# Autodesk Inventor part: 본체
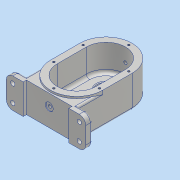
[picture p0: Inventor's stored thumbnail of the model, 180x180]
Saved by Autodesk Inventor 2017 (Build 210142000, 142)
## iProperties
Part Number: 본체
Material: 알루미늄 6061
Document SubType Name: Modeling
Designer: MRC
Density: 2.7 g/cm^3
Appearance: 알루미늄 - 평지
Mass: 755.763 g
Surface Area: 583.989 cm^2
Volume: 279.912 cm^3
Author: MRC
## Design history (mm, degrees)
sketch "스케치1"
  geometry: L1 (0, 0)-(0, 45); L2 (40, 0)-(40, 45); L3 (-40, 45)-(-40, 0); A1 r 40 centre (0, 0) between (-40, 0) and (40, 0); A2 r 40 centre (0, 45) between (40, 45) and (-40, 45); 1 further point
  constraints: 8 end point, 4 point on circle, 4 tangent, 2 centre point, 1 midpoint, 1 parallel, 1 vertical
  dimensions: "d0" = 80 distance between parallel lines of L3 L2; "d1" = 45 distance of L1.start L1.end
extrude "돌출1" new body sketch "스케치1" distance "d2" = 49; taper "d3" = 0 deg
feature "쉘1" dims "d4" = 10, "d113" = 8
sketch "스케치2"
  geometry: L1 (0, 45)-(0, 0); L2 (-26, 45)-(-26, 0); L3 (26, 0)-(26, 45); A1 r 40 centre (0, 0) between (-40, 0) and (40, 0) reference; A2 r 40 centre (0, 45) between (40, 45) and (-40, 45) reference; A3 r 26 centre (0, 45) between (26, 45) and (-26, 45); A4 r 26 centre (0, 0) between (-26, 0) and (26, 0); 1 further point
  constraints: 8 end point, 4 point on circle, 4 tangent, 2 centre point, 1 midpoint, 1 parallel, 1 vertical
  dimensions: "d5" = 52 distance between parallel lines of L3 L2
extrude "돌출2" join sketch "스케치2" distance "d6" = 11; taper "d7" = 0 deg
sketch "스케치3"
  geometry: L1 (-26, 75)-(26, 75); L2 (26, 75)-(26, 15); L3 (26, 15)-(-26, 15); L4 (-26, 15)-(-26, 75); A1 r 26 centre (0, 45) between (26, 45) and (-26, 45) reference; 2 further points
  constraints: 8 end point, 2 midpoint, 2 parallel, 1 horizontal, 1 horizontal alignment, 1 perpendicular, 1 vertical alignment
  dimensions: "d8" = 30 distance of A1.centre point (0, 15); "d9" = 52 distance of L2.end L3.end
extrude "돌출3" cut sketch "스케치3" distance "d10" = 3; taper "d11" = 0 deg
sketch "스케치4"
  geometry: A1 r 30 centre (0, -45) between (-30, -45) and (30, -45) reference; 1 further point
  constraints: 1 coincident
hole "구멍1" sketch "스케치4" at (0, -45) diameter "d12" = 20; stored, may be unused: countersink angle "d16" = 90 deg, drill point angle "d18" = 0 deg; dims "d13" = 6, "d14" = 28, "d15" = 8, "d17" = 12
sketch "스케치5"
  geometry: C1 r 14 at (0, 0); A1 r 30 centre (0, 0) between (30, 0) and (-30, 0) reference
  constraints: 1 centre point, 1 coincident
  dimensions: "d19" = 28 diameter of C1
extrude "돌출4" cut sketch "스케치5" distance "d20" = 8; taper "d21" = 0 deg
sketch "스케치6"
  geometry: A1 r 26 centre (0, 45) between (26, 45) and (-26, 45) reference; 2 further points
  constraints: 1 coincident
hole "구멍2" sketch "스케치6" at (0, 45) diameter "d22" = 22; stored, may be unused: countersink angle "d26" = 90 deg, drill point angle "d28" = 0 deg; dims "d23" = 6, "d24" = 28, "d25" = 4, "d27" = 12
sketch "스케치7"
  geometry: L1 (-61, -37)-(61, -37); L2 (61, -37)-(61, -47); L3 (61, -47)-(-61, -47); L4 (-61, -47)-(-61, -37); L5 (-40, 0)-(-40, -37); L6 (40, 0)-(40, -37); A1 r 26 centre (0, 45) between (26, 45) and (-26, 45) reference; A2 r 26 centre (0, 0) between (-26, 0) and (26, 0) reference; A3 r 40 centre (0, 0) between (-40, 0) and (40, 0) reference; 1 further point
  constraints: 12 end point, 2 parallel, 2 perpendicular, 2 point on line, 1 horizontal, 1 midpoint, 1 point on circle, 1 tangent, 1 vertical, 1 vertical alignment
  dimensions: "d29" = 10 distance of L3.end L1.start; "d30" = 47 distance from line of L3 A2.centre; "d31" = 122 distance of L2.end L3.end
extrude "돌출5" join sketch "스케치7" distance "d32" = 46; taper "d33" = 0 deg
sketch "스케치11"
  geometry: L1 (-61, -47)-(61, -47) reference; L2 (-35, -42)-(35, -42); L3 (35, -42)-(35, -47); L4 (35, -47)-(-35, -47); L5 (-35, -47)-(-35, -42); 3 further points
  constraints: 8 end point, 4 midpoint, 2 parallel, 1 horizontal, 1 perpendicular, 1 vertical alignment
  dimensions: "d39" = 5 distance of L2.end L3.end; "d40" = 70 distance of L3.end L4.end
extrude "돌출7" cut sketch "스케치11" stored distance "d41" = 38; taper "d42" = 0 deg
node "작업 평면1"
sketch "스케치12"
  geometry: C1 r 6 at (-61, 28); 1 further point
  constraints: 1 centre point
  dimensions: "d44" = 12 diameter of C1; "d45" = 21 distance of point (-61, 49) C1.centre
extrude "돌출8" join sketch "스케치12" stored distance "d46" = 12 (= d44); taper "d47" = 0 deg
sketch "스케치13"
  geometry: C1 r 6 at (0, 0) reference; 2 further points
  constraints: 1 coincident
hole "구멍3" sketch "스케치13" at (0, 0) diameter "d48" = 4.917; stored, may be unused: countersink angle "d52" = 90 deg, drill point angle "d54" = 0 deg; dims "d49" = 12, "d50" = 28, "d51" = 4, "d53" = 17.1
sketch "스케치14"
  geometry: A1 r 30 centre (0, 45) between (30, 45) and (-30, 45) reference; A2 r 30 centre (0, 0) between (-30, 0) and (30, 0) reference; 6 further points
  constraints: 4 horizontal alignment, 2 vertical alignment
  dimensions: "d55" = 35 distance of point (0, 80) A1.centre; "d56" = 35 distance of A2.centre point (0, -35); "d83" = 35 distance of point (-35, 45) A1.centre; "d84" = 35 distance of A2.centre point (-35, 0); "d85" = 35 distance of point (35, 0) A2.centre; "d86" = 35 distance of point (35, 45) A1.centre
hole "구멍4" sketch "스케치14" at (0, 80), (0, -35), (-35, 45), (-35, 0), (35, 0), (35, 45) diameter "d57" = 3.242; stored, may be unused: countersink angle "d61" = 90 deg, drill point angle "d63" = 118 deg; dims "d58" = 8, "d59" = 28, "d60" = 4, "d62" = 10
sketch "스케치15"
  geometry: C1 r 6 at (35, -18); 1 further point
  constraints: 1 centre point, 1 vertical alignment
  dimensions: "d64" = 12 diameter of C1; "d65" = 21 distance of C1.centre point (35, 3)
extrude "돌출9" cut sketch "스케치15" distance "d66" = 1; taper "d67" = 0 deg
sketch "스케치16"
  geometry: C1 r 6 at (0, 0) reference; 2 further points
  constraints: 1 coincident
hole "구멍5" sketch "스케치16" at (0, 0) diameter "d68" = 4.917; stored, may be unused: countersink angle "d72" = 90 deg, drill point angle "d74" = 0 deg; dims "d69" = 12, "d70" = 28, "d71" = 4, "d73" = 17.1
sketch "스케치17"
  geometry: C1 r 14 at (0, 45) reference; 2 further points
  constraints: 1 vertical alignment
  dimensions: "d75" = 20 distance of point (0, 65) C1.centre
hole "구멍6" sketch "스케치17" at (0, 65) diameter "d76" = 3.242; stored, may be unused: countersink angle "d80" = 90 deg, drill point angle "d82" = 118 deg; dims "d77" = 8, "d78" = 28, "d79" = 4, "d81" = 10
fillet "모깎기1" dims "d87" = 10
fillet "모깎기2" dims "d88" = 3, "d112" = 5
chamfer "모따기1" distance "d89" = 1; stored, may be unused: second distance "d90" = 2, angle "d91" = 45 deg
fillet "모깎기3" dims "d92" = 0.3, "d93" = 3
chamfer "모따기2" distance "d94" = 1; stored, may be unused: second distance "d95" = 2, angle "d96" = 45 deg
sketch "스케치18"
  geometry: A1 r 7 centre (11, 7) between (11, 0) and (18, 7) reference; A2 r 7 centre (11, 33) between (18, 33) and (11, 40) reference; 3 further points
  constraints: 2 coincident
hole "구멍7" sketch "스케치18" at (11, 7), (11, 33) diameter "d97" = 6.6; stored, may be unused: countersink angle "d101" = 90 deg, drill point angle "d103" = 118 deg; dims "d98" = 6.6, "d99" = 11, "d100" = 2, "d102" = 10
fillet "모깎기4" dims "d104" = 3
sketch "스케치19"
  geometry: L1 (-35, -47)-(-51, -47) reference; A1 r 37 centre (0, 45) between (37, 45) and (-37, 45) reference; 1 further point
  constraints: 1 vertical alignment, 1 other
  dimensions: "d105" = 12 distance from line of point (0, -35) L1
feature "엠보싱1" sketch "스케치19" dims "d106" = 0.5, "d107" = 0
chamfer "모따기3" distance "d108" = 1; stored, may be unused: second distance "d109" = 2, angle "d110" = 45 deg
fillet "모깎기5" dims "d111" = 3
node "솔리드1"
mirror "미러1"
pattern_circular "원형 패턴1" dims angle "d115" = 360 deg
other parameters: "d43" = -135
